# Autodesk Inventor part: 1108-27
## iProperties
Created: 2007-03
Part Number: 1108-27
Document SubType Name: Modeling
Designer: Andy Moles
Material: Steel
Mass: 0.346522 g
Surface Area: 1.1133 cm^2
Volume: 0.044143 cm^3
Density: 7.85 g/cm^3
Author: Andy Moles
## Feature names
1. Base1
